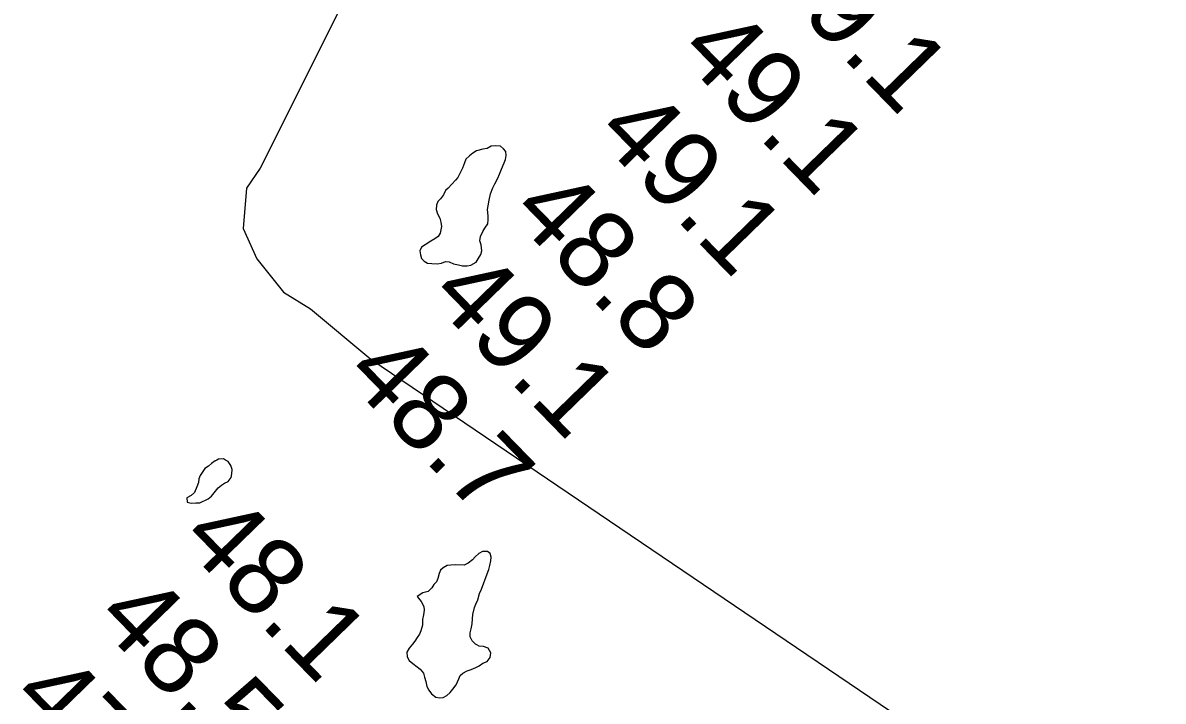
# Model space of a CAD drawing. Extents: x 3180038 to 3217926, y 922069 to 947485.
# Drawn here: x 3194156 to 3195138, y 940267 to 940851 of the extents above; entities that cross this region are included whole.
import ezdxf

# ---------------------------------------------------------------- set-up
doc = ezdxf.new("R2010")
doc.units = 0
doc.layers.add('V-RIVR-RANG', color=7, linetype='Continuous')
doc.layers.add('V-TOPO-SHOR', color=7, linetype='Continuous')

msp = doc.modelspace()

# ---------------------------------------------------------------- linework, layer by layer
at = {"layer": 'V-TOPO-SHOR'}
for points in [[(3194736.83, 941489.4), (3194449.84, 940904.49), (3194360.32, 940725.43), (3194348.76, 940708.11), (3194345.88, 940673.45), (3194357.43, 940647.46), (3194380.53, 940618.58), (3194403.64, 940604.14), (3194455.62, 940560.82), (3194911.91, 940251.81), (3195018.77, 940173.84), (3195389.13, 939921.26)], [(3194522.28, 940708.04), (3194519.98, 940706.06), (3194518.23, 940702.36), (3194515.63, 940698.95), (3194513.33, 940696.69), (3194512.16, 940693.55), (3194511.85, 940689.84), (3194512.96, 940686.12), (3194515.22, 940682.39), (3194516.05, 940678.95), (3194516.59, 940675.23), (3194515.41, 940669.53), (3194513.67, 940666.69), (3194510.8, 940664.42), (3194507.35, 940662.45), (3194502.47, 940659.35), (3194499.32, 940657.37), (3194497.86, 940654.24), (3194498.41, 940650.81), (3194499.24, 940647.66), (3194501.51, 940645.36), (3194504.35, 940643.62), (3194508.35, 940643.3), (3194512.92, 940642.98), (3194516.63, 940643.53), (3194520.07, 940644.93), (3194523.21, 940644.62), (3194526.91, 940643.16), (3194531.19, 940642.27), (3194534.61, 940641.39), (3194538.61, 940641.35), (3194541.76, 940641.9), (3194546.35, 940644.44), (3194548.09, 940647.28), (3194550.4, 940650.98), (3194551.28, 940654.11), (3194550.75, 940659.26), (3194549.63, 940662.69), (3194550.23, 940666.69), (3194551.98, 940670.96), (3194553.72, 940673.8), (3194556.32, 940677.5), (3194556.63, 940680.92), (3194556.66, 940684.35), (3194556.13, 940689.78), (3194556.72, 940692.92), (3194557.62, 940697.77), (3194558.8, 940703.19), (3194560.84, 940708.31), (3194562.3, 940712.02), (3194564.91, 940716.85), (3194566.36, 940720.27), (3194568.11, 940724.54), (3194570.44, 940729.95), (3194571.6, 940732.8), (3194572.2, 940736.22), (3194571.94, 940739.65), (3194569.96, 940741.95), (3194567.4, 940744.26), (3194562.84, 940744.58), (3194559.41, 940744.32), (3194555.96, 940742.35), (3194552.25, 940741.8), (3194546.52, 940740.42), (3194543.36, 940738.16), (3194540.49, 940735.9), (3194537.61, 940733.06), (3194536.44, 940729.93), (3194534.69, 940725.37), (3194532.66, 940721.39), (3194530.63, 940717.41), (3194528.61, 940715.13), (3194522.28, 940708.04)], [(3194308.83, 940460.93), (3194307.66, 940457.79), (3194307.35, 940454.65), (3194305.89, 940450.95), (3194303.86, 940446.11), (3194300.98, 940443.56), (3194297.25, 940441.59), (3194297.51, 940437.87), (3194300.93, 940436.99), (3194304.93, 940437.24), (3194308.36, 940437.22), (3194315.53, 940440.59), (3194318.4, 940443.14), (3194320.71, 940445.98), (3194324.17, 940450.24), (3194327.05, 940452.5), (3194329.63, 940454.19), (3194332.78, 940455.6), (3194335.38, 940459.01), (3194335.98, 940462.14), (3194336.29, 940465.86), (3194335.17, 940469.29), (3194332.92, 940472.74), (3194330.62, 940474.07)], [(3194330.62, 940474.07), (3194328.93, 940475.05), (3194325.22, 940474.8), (3194324.65, 940474.8), (3194323.21, 940473.96), (3194322.06, 940473.39), (3194321.78, 940473.39), (3194318.62, 940471.14), (3194316.03, 940468.87), (3194312.88, 940466.89), (3194308.83, 940460.93)], [(3194547.06, 940314.98), (3194545.67, 940315.69), (3194542.83, 940318.57), (3194541.14, 940322.01), (3194541.17, 940325.43), (3194542.05, 940328.86), (3194542.94, 940333.13), (3194543.26, 940337.42), (3194543.58, 940341.13), (3194545.05, 940347.11), (3194546.22, 940349.96), (3194547.67, 940353.67), (3194549.15, 940359.08), (3194550.89, 940363.07), (3194552.93, 940368.48), (3194554.68, 940373.04), (3194555.85, 940376.17), (3194557.3, 940379.87), (3194558.19, 940383.29), (3194559.08, 940387.29), (3194559.39, 940390.43), (3194558.55, 940393.58), (3194556, 940395.31), (3194551.71, 940395.34), (3194548.56, 940393.65), (3194545.39, 940390.82), (3194543.08, 940388.27), (3194539.35, 940385.44), (3194535.91, 940383.75), (3194528.48, 940383.81), (3194524.48, 940383.55), (3194521.34, 940383.29), (3194517.89, 940381.32), (3194515.59, 940379.34), (3194514.43, 940376.49), (3194513.25, 940372.21), (3194512.09, 940369.37), (3194510.07, 940367.1), (3194508.33, 940363.97), (3194505.17, 940360.85), (3194500.59, 940359.74), (3194495.7, 940356.64)], [(3194495.7, 940356.64), (3194499.1, 940352.33), (3194501.35, 940348.02), (3194501.61, 940344.88), (3194501.01, 940340.89), (3194500.12, 940336.89), (3194500.09, 940332.04), (3194498.62, 940327.19), (3194497.46, 940324.34), (3194495.72, 940321.22), (3194493.69, 940318.09), (3194491.67, 940315.53), (3194488.79, 940312.13), (3194486.76, 940308.72), (3194487.02, 940304.71), (3194488.71, 940301.56), (3194491.83, 940298.96), (3194495.52, 940296.08), (3194498.08, 940294.06), (3194500.91, 940290.61), (3194502.02, 940287.17), (3194503.14, 940283.45), (3194503.96, 940279.16), (3194505.65, 940276), (3194507.91, 940272.84), (3194511.6, 940269.96), (3194514.74, 940269.36), (3194517.89, 940269.62), (3194521.04, 940271.31), (3194523.92, 940273.86), (3194526.23, 940276.99), (3194529.11, 940280.68), (3194531.44, 940285.8), (3194532.6, 940288.65), (3194534.9, 940290.63), (3194538.63, 940292.6), (3194542.07, 940293.72), (3194546.08, 940295.4), (3194548.95, 940297.09), (3194552.11, 940299.35), (3194555.83, 940300.75), (3194558.43, 940304.16), (3194559.03, 940308.16), (3194556.78, 940312.17), (3194552.79, 940313.63), (3194549.08, 940313.95), (3194547.06, 940314.98)]]:
    msp.add_lwpolyline(points, dxfattribs=at)

# ---------------------------------------------------------------- texts
at = {"layer": 'V-RIVR-RANG'}
for s, p in [('49.1', (3194790.35, 940893.78)), ('49.1', (3194718.84, 940823.88)), ('49.1', (3194647.32, 940753.99)), ('48.8', (3194574.15, 940685.79)), ('49.1', (3194504.3, 940614.19)), ('48.7', (3194431.13, 940545.99)), ('48.1', (3194289.75, 940404.5)), ('48.5', (3194216.58, 940336.3)), ('47.6', (3194143.78, 940267.72))]:
    msp.add_text(s, height=67, rotation=314.20833, dxfattribs=at).set_placement(p)

doc.saveas('drawing.dxf')
